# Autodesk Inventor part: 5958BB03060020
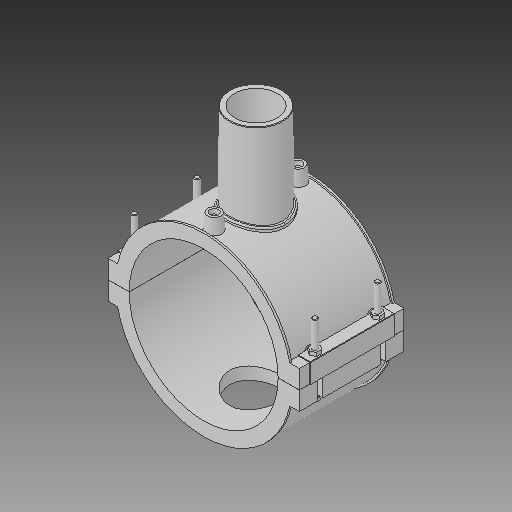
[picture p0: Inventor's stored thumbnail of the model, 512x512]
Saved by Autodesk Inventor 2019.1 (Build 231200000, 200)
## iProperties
Created: 2017-07
Part Number: 5958BB03060020
Material: Generic
Description: PLASSON BRANCH SADDLE 6'' x 2''
Document SubType Name: Modeling
Designer: KIM
Mass: 764.267 g
Surface Area: 1930.38 cm^2
Volume: 764.267 cm^3
Density: 1 g/cm^3
Appearance: Default
Author: KIM
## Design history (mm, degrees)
derived "5958B.ipt"
feature "Solid1::5958B.ipt"
feature "Solid2::5958B.ipt"
feature "Solid3::5958B.ipt"
tag "TaggingFeature1"
body "Solid1"
body "Solid2"
body "Solid3"
other parameters: "d_" = 168, "B_" = 215.9, "H_" = 97.028, "L_" = 118.11, "d_t" = 6, "d_1" = 60.1, "H_1" = 83.566, "d1" = 194.924, "d148" = 4.2, "d160" = 4.2, "d0" = 168, "d2" = 215.9, "d3" = 42, "d4" = 118.11, "d5" = 0, "d6" = 0.1, "d8" = 0, "d19" = 6, "d20" = 6, "d21" = 70.866, "d23" = 0, "d24" = 35.433, "d26" = 0, "d27" = 3, "d28" = 3, "d29" = 3, "d30" = 56, "d31" = 6, "d32" = 0, "d33" = 0, "d34" = 0.6, "d40" = 101.36048, "d41" = 66.11, "d43" = 0, "d45" = 0, "d47" = 194.49, "d48" = 60.1, "d50" = 0, "d70" = 15, "d72" = 0, "d73" = 6, "d75" = 5, "d76" = 0, "d77" = 8.4, "d78" = 114, "d79" = 15, "d80" = 47.244, "d82" = 5 deg, "d84" = 4, "d85" = 14, "d86" = 0, "d87" = 3, "d88" = 0, "d89" = 1, "d90" = 1, "d91" = 94.488, "d92" = 0, "d93" = 0.5, "d94" = 88.42105, "d96" = 198.82248, "d97" = 2.3622, "d98" = 0, "d102" = 1.803, "d103" = 48.08, "d105" = 0, "d109" = -32.34267, "d117" = 0.601, "d120" = 140 deg, "d121" = 24.228, "d122" = 20 deg, "d123" = 389.848, "d124" = 116.9544, "d126" = 0, "d143" = 176.4, "d150" = 30.24, "d159" = 5.3848, "d161" = 4.2, "d162" = 70.866, "d163" = 0, "d167" = 33.6, "d168" = 88.60182, "d173" = 1, "d175" = 84, "d176" = 20 deg, "d177" = 11.76, "d178" = 26.924, "d180" = 0, "d185" = 38.38575, "d186" = 38.38575, "d187" = 97.462, "d188" = 8.0772, "d189" = 11.76, "d190" = 0, "d191" = 146.193, "d200" = 13.462, "d202" = 0, "d216" = 106.299, "d217" = 0, "d221" = 43.7007, "d222" = 11.76, "d223" = 7.056, "d224" = 84, "d225" = 7.056, "d227" = 24.192, "d230" = 104.16, "d236" = 11.5 deg, "d238" = 20 deg, "d239" = 11.76, "d240" = 0, "d241" = 0, "d242" = 6.2484
